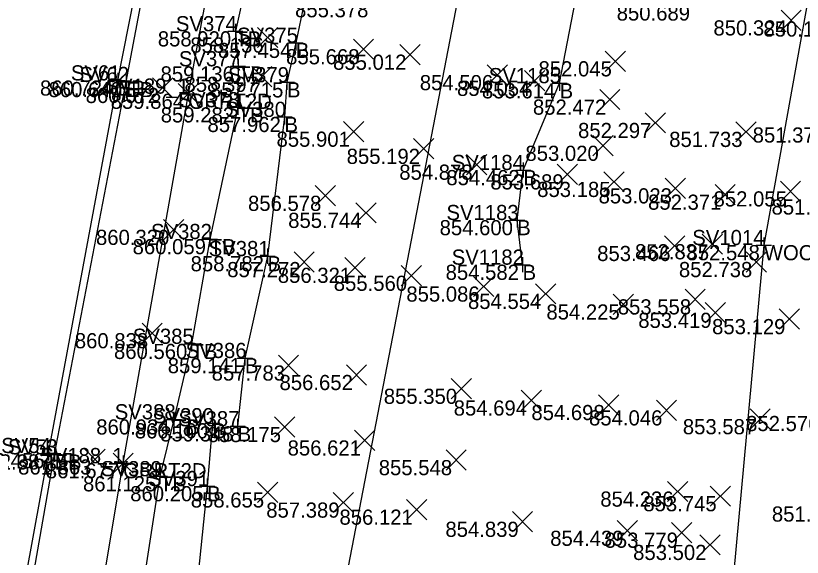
# Model space of a CAD drawing. Extents: x 2228183 to 2230895, y 679226 to 682223.
# Drawn here: x 2228291.3 to 2228343.2, y 680434.6 to 680470.3 of the extents above; entities that cross this region are included whole.
import ezdxf

# ---------------------------------------------------------------- set-up
doc = ezdxf.new("R2010")
doc.units = 0
for name, color, linetype in [('PV_X_EOP', 7, 'Continuous'), ('PV_X_Shoulder_Aggregate', 7, 'Continuous'), ('RD_X_GR_Rt', 7, 'Continuous'), ('SC_Scratch1', 7, 'Continuous'), ('SV_P_Control_Cells_Set', 7, 'Continuous'), ('SV_X_Break_Lines', 7, 'Continuous'), ('SV_X_Random_Point', 7, 'Continuous'), ('SV_X_Shot_Marker', 7, 'Continuous'), ('SV_X_Text_Comment', 7, 'Continuous'), ('SV_X_Top_of_Bank', 7, 'Continuous'), ('UT_X_Telecom', 7, 'Continuous'), ('VG_X_Tree_Line_Rt', 7, 'Continuous')]:
    doc.layers.add(name, color=color, linetype=linetype)

msp = doc.modelspace()

# ---------------------------------------------------------------- linework, layer by layer
at = {"layer": 'PV_X_EOP'}
msp.add_lwpolyline([(2228272.958, 680193.788), (2228272.514, 680218.749), (2228272.761, 680243.66), (2228273.456, 680268.53), (2228274.726, 680293.686), (2228276.435, 680318.586), (2228278.817, 680343.424), (2228281.861, 680368.095), (2228285.158, 680392.512), (2228289.018, 680417.009), (2228293.5, 680441.465), (2228298.055, 680466.05), (2228302.846, 680490.329), (2228307.636, 680514.848), (2228312.366, 680539.332), (2228317.173, 680563.701), (2228322.066, 680588.07), (2228326.883, 680612.686), (2228331.837, 680637.002), (2228336.903, 680661.667), (2228341.796, 680685.984)], dxfattribs=at)
at = {"layer": 'PV_X_Shoulder_Aggregate'}
msp.add_lwpolyline([(2228273.386, 680193.772), (2228272.957, 680218.691), (2228273.264, 680243.644), (2228274.133, 680268.478), (2228275.472, 680293.621), (2228277.239, 680318.511), (2228279.649, 680343.317), (2228282.622, 680367.988), (2228285.854, 680392.371), (2228289.575, 680416.853), (2228293.89, 680441.38), (2228298.61, 680465.949), (2228303.2, 680490.238), (2228308.065, 680514.741), (2228313.026, 680539.169), (2228317.996, 680563.53), (2228322.869, 680587.896), (2228327.71, 680612.549), (2228332.443, 680636.855), (2228337.368, 680661.526), (2228342.398, 680685.817)], dxfattribs=at)
at = {"layer": 'RD_X_GR_Rt'}
msp.add_lwpolyline([(2228290.359, 680391.22), (2228294.274, 680415.932), (2228298.414, 680440.801), (2228302.718, 680465.177), (2228307.188, 680489.321), (2228312.206, 680513.859), (2228316.706, 680538.587), (2228321.519, 680562.878), (2228326.574, 680587.113), (2228331.32, 680611.864), (2228336.079, 680636.156), (2228341.093, 680660.882), (2228346.244, 680685.06), (2228350.849, 680709.572), (2228355.751, 680733.95), (2228357.804, 680743.718), (2228360.585, 680755.706), (2228364.08, 680768.892), (2228368.125, 680781.145)], dxfattribs=at)
at = {"layer": 'SV_X_Break_Lines'}
for points in [[(2228314.747, 680495.992), (2228314.241, 680492.773), (2228314.211, 680488.538), (2228311.578, 680478.889), (2228311.017, 680474.372), (2228309.793, 680468.535), (2228309.215, 680465.931), (2228309.05, 680463.646), (2228307.936, 680454.458), (2228306.438, 680447.736), (2228305.961, 680443.231)], [(2228324.748, 680453.895), (2228324.393, 680456.839), (2228324.797, 680460.14), (2228327.19, 680465.87), (2228328.374, 680472.025), (2228328.363, 680475.549), (2228327.9, 680480.992), (2228324.768, 680483.725), (2228321.985, 680484.931)], [(2228304.297, 680443.433), (2228303.951, 680439.284), (2228303.202, 680431.998), (2228302.174, 680428.001), (2228301.552, 680423.556), (2228300.767, 680417.736), (2228301.038, 680414.553), (2228299.654, 680408.328), (2228299.055, 680402.795), (2228298.646, 680389.665)]]:
    msp.add_lwpolyline(points, dxfattribs=at)
at = {"layer": 'SV_X_Random_Point'}
for p, q in [((2228341.786, 680469.35), (2228343.12, 680470.685)), ((2228341.786, 680470.685), (2228343.12, 680469.35)), ((2228307.28, 680468.218), (2228308.614, 680469.553)), ((2228307.28, 680469.553), (2228308.614, 680468.218)), ((2228313.594, 680467.448), (2228314.928, 680468.783)), ((2228313.594, 680468.783), (2228314.928, 680467.448)), ((2228316.662, 680467.088), (2228317.996, 680468.423)), ((2228316.662, 680468.423), (2228317.996, 680467.088)), ((2228330.203, 680466.652), (2228331.537, 680467.987)), ((2228330.203, 680467.987), (2228331.537, 680466.652)), ((2228306.891, 680465.627), (2228308.225, 680466.962)), ((2228306.891, 680466.962), (2228308.225, 680465.627)), ((2228322.409, 680465.74), (2228323.743, 680467.075)), ((2228322.409, 680467.075), (2228323.743, 680465.74)), ((2228300.349, 680464.895), (2228301.683, 680466.23)), ((2228300.349, 680466.23), (2228301.683, 680464.895)), ((2228324.88, 680465.362), (2228326.214, 680466.697)), ((2228324.88, 680466.697), (2228326.214, 680465.362)), ((2228302.051, 680464.51), (2228303.385, 680465.845)), ((2228302.051, 680465.845), (2228303.385, 680464.51)), ((2228329.836, 680464.125), (2228331.17, 680465.46)), ((2228329.836, 680465.46), (2228331.17, 680464.125)), ((2228332.835, 680462.584), (2228334.169, 680463.919)), ((2228332.835, 680463.919), (2228334.169, 680462.584)), ((2228312.942, 680462.008), (2228314.276, 680463.343)), ((2228312.942, 680463.343), (2228314.276, 680462.008)), ((2228338.811, 680461.994), (2228340.145, 680463.329)), ((2228338.811, 680463.329), (2228340.145, 680461.994)), ((2228317.557, 680460.876), (2228318.891, 680462.211)), ((2228317.557, 680462.211), (2228318.891, 680460.876)), ((2228329.384, 680461.077), (2228330.718, 680462.412)), ((2228329.384, 680462.412), (2228330.718, 680461.077)), ((2228321.052, 680459.832), (2228322.386, 680461.167)), ((2228321.052, 680461.167), (2228322.386, 680459.832)), ((2228327.039, 680459.191), (2228328.373, 680460.526)), ((2228327.039, 680460.526), (2228328.373, 680459.191)), ((2228330.115, 680458.694), (2228331.449, 680460.029)), ((2228330.115, 680460.029), (2228331.449, 680458.694)), ((2228334.156, 680458.269), (2228335.49, 680459.604)), ((2228334.156, 680459.604), (2228335.49, 680458.269)), ((2228311.08, 680457.776), (2228312.414, 680459.111)), ((2228311.08, 680459.111), (2228312.414, 680457.776)), ((2228337.435, 680457.853), (2228338.769, 680459.188)), ((2228337.435, 680459.188), (2228338.769, 680457.853)), ((2228341.742, 680458.068), (2228343.076, 680459.403)), ((2228341.742, 680459.403), (2228343.076, 680458.068)), ((2228313.751, 680456.651), (2228315.085, 680457.986)), ((2228313.751, 680457.986), (2228315.085, 680456.651)), ((2228301.072, 680455.531), (2228302.406, 680456.866)), ((2228301.072, 680456.866), (2228302.406, 680455.531)), ((2228336.586, 680454.581), (2228337.92, 680455.916)), ((2228336.586, 680455.916), (2228337.92, 680454.581)), ((2228334.103, 680454.469), (2228335.437, 680455.804)), ((2228334.103, 680455.804), (2228335.437, 680454.469)), ((2228309.684, 680453.404), (2228311.018, 680454.739)), ((2228309.684, 680454.739), (2228311.018, 680453.404)), ((2228313.027, 680453.027), (2228314.361, 680454.362)), ((2228313.027, 680454.362), (2228314.361, 680453.027)), ((2228339.488, 680453.406), (2228340.822, 680454.741)), ((2228339.488, 680454.741), (2228340.822, 680453.406)), ((2228316.748, 680452.501), (2228318.082, 680453.836)), ((2228316.748, 680453.836), (2228318.082, 680452.501)), ((2228321.522, 680451.79), (2228322.856, 680453.125)), ((2228321.522, 680453.125), (2228322.856, 680451.79)), ((2228325.603, 680451.305), (2228326.937, 680452.64)), ((2228325.603, 680452.64), (2228326.937, 680451.305)), ((2228335.457, 680450.944), (2228336.791, 680452.279)), ((2228335.457, 680452.279), (2228336.791, 680450.944)), ((2228330.722, 680450.609), (2228332.056, 680451.944)), ((2228330.722, 680451.944), (2228332.056, 680450.609)), ((2228336.793, 680450.057), (2228338.127, 680451.392)), ((2228336.793, 680451.392), (2228338.127, 680450.057)), ((2228341.659, 680449.642), (2228342.993, 680450.977)), ((2228341.659, 680450.977), (2228342.993, 680449.642)), ((2228299.663, 680448.711), (2228300.997, 680450.046)), ((2228299.663, 680450.046), (2228300.997, 680448.711)), ((2228308.65, 680446.58), (2228309.984, 680447.915)), ((2228308.65, 680447.915), (2228309.984, 680446.58)), ((2228313.131, 680445.953), (2228314.465, 680447.288)), ((2228313.131, 680447.288), (2228314.465, 680445.953)), ((2228320.045, 680445.043), (2228321.379, 680446.378)), ((2228320.045, 680446.378), (2228321.379, 680445.043)), ((2228324.662, 680444.271), (2228325.996, 680445.606)), ((2228324.662, 680445.606), (2228325.996, 680444.271)), ((2228329.762, 680443.972), (2228331.096, 680445.307)), ((2228329.762, 680445.307), (2228331.096, 680443.972)), ((2228333.567, 680443.62), (2228334.901, 680444.955)), ((2228333.567, 680444.955), (2228334.901, 680443.62)), ((2228339.742, 680443.038), (2228341.076, 680444.373)), ((2228339.742, 680444.373), (2228341.076, 680443.038)), ((2228308.39, 680442.522), (2228309.724, 680443.857)), ((2228308.39, 680443.857), (2228309.724, 680442.522)), ((2228313.674, 680441.635), (2228315.008, 680442.97)), ((2228313.674, 680442.97), (2228315.008, 680441.635)), ((2228295.888, 680440.382), (2228297.222, 680441.717)), ((2228295.888, 680441.717), (2228297.222, 680440.382)), ((2228297.747, 680440.134), (2228299.081, 680441.469)), ((2228297.747, 680441.469), (2228299.081, 680440.134)), ((2228319.7, 680440.337), (2228321.034, 680441.672)), ((2228319.7, 680441.672), (2228321.034, 680440.337)), ((2228307.277, 680438.205), (2228308.611, 680439.54)), ((2228307.277, 680439.54), (2228308.611, 680438.205)), ((2228334.308, 680438.262), (2228335.642, 680439.597)), ((2228334.308, 680439.597), (2228335.642, 680438.262)), ((2228337.111, 680437.957), (2228338.445, 680439.292)), ((2228337.111, 680439.292), (2228338.445, 680437.957)), ((2228312.266, 680437.536), (2228313.6, 680438.871)), ((2228312.266, 680438.871), (2228313.6, 680437.536)), ((2228317.092, 680437.07), (2228318.426, 680438.405)), ((2228317.092, 680438.405), (2228318.426, 680437.07)), ((2228324.078, 680436.269), (2228325.412, 680437.604)), ((2228324.078, 680437.604), (2228325.412, 680436.269)), ((2228330.987, 680435.674), (2228332.321, 680437.009)), ((2228330.987, 680437.009), (2228332.321, 680435.674)), ((2228334.57, 680435.55), (2228335.904, 680436.885)), ((2228334.57, 680436.885), (2228335.904, 680435.55)), ((2228336.443, 680434.743), (2228337.777, 680436.078)), ((2228336.443, 680436.078), (2228337.777, 680434.743))]:
    msp.add_line(p, q, dxfattribs=at)
at = {"layer": 'SV_X_Shot_Marker'}
for p, q in [((2228305.315, 680469.295), (2228306.315, 680469.295)), ((2228305.815, 680469.795), (2228305.815, 680468.795)), ((2228305.815, 680469.295), (2228305.815, 680469.295)), ((2228309.793, 680469.035), (2228309.793, 680468.035)), ((2228309.293, 680468.535), (2228310.293, 680468.535)), ((2228309.793, 680468.535), (2228309.793, 680468.535)), ((2228305.987, 680467.483), (2228305.987, 680466.483)), ((2228305.487, 680466.983), (2228306.487, 680466.983)), ((2228305.987, 680466.983), (2228305.987, 680466.983)), ((2228298.055, 680466.55), (2228298.055, 680465.55)), ((2228298.61, 680466.449), (2228298.61, 680465.449)), ((2228309.215, 680466.431), (2228309.215, 680465.431)), ((2228327.19, 680466.37), (2228327.19, 680465.37)), ((2228297.555, 680466.05), (2228298.555, 680466.05)), ((2228298.055, 680466.05), (2228298.055, 680466.05)), ((2228298.11, 680465.949), (2228299.11, 680465.949)), ((2228298.61, 680465.949), (2228298.61, 680465.949)), ((2228302.718, 680465.677), (2228302.718, 680464.677)), ((2228308.715, 680465.931), (2228309.715, 680465.931)), ((2228309.215, 680465.931), (2228309.215, 680465.931)), ((2228326.69, 680465.87), (2228327.69, 680465.87)), ((2228327.19, 680465.87), (2228327.19, 680465.87)), ((2228302.218, 680465.177), (2228303.218, 680465.177)), ((2228302.718, 680465.177), (2228302.718, 680465.177)), ((2228305.966, 680464.779), (2228305.966, 680463.779)), ((2228305.466, 680464.279), (2228306.466, 680464.279)), ((2228305.966, 680464.279), (2228305.966, 680464.279)), ((2228309.05, 680464.146), (2228309.05, 680463.146)), ((2228308.55, 680463.646), (2228309.55, 680463.646)), ((2228309.05, 680463.646), (2228309.05, 680463.646)), ((2228324.797, 680460.64), (2228324.797, 680459.64)), ((2228324.297, 680460.14), (2228325.297, 680460.14)), ((2228324.797, 680460.14), (2228324.797, 680460.14)), ((2228324.393, 680457.339), (2228324.393, 680456.339)), ((2228323.893, 680456.839), (2228324.893, 680456.839)), ((2228324.393, 680456.839), (2228324.393, 680456.839)), ((2228304.125, 680456.086), (2228304.125, 680455.086)), ((2228303.625, 680455.586), (2228304.625, 680455.586)), ((2228304.125, 680455.586), (2228304.125, 680455.586)), ((2228340.655, 680455.686), (2228340.655, 680454.686)), ((2228307.936, 680454.958), (2228307.936, 680453.958)), ((2228340.155, 680455.186), (2228341.155, 680455.186)), ((2228340.655, 680455.186), (2228340.655, 680455.186)), ((2228307.436, 680454.458), (2228308.436, 680454.458)), ((2228307.936, 680454.458), (2228307.936, 680454.458)), ((2228324.748, 680454.395), (2228324.748, 680453.395)), ((2228324.248, 680453.895), (2228325.248, 680453.895)), ((2228324.748, 680453.895), (2228324.748, 680453.895)), ((2228302.925, 680449.172), (2228302.925, 680448.172)), ((2228302.425, 680448.672), (2228303.425, 680448.672)), ((2228302.925, 680448.672), (2228302.925, 680448.672)), ((2228306.438, 680448.236), (2228306.438, 680447.236)), ((2228305.938, 680447.736), (2228306.938, 680447.736)), ((2228306.438, 680447.736), (2228306.438, 680447.736)), ((2228301.763, 680444.189), (2228301.763, 680443.189)), ((2228304.297, 680443.933), (2228304.297, 680442.933)), ((2228301.263, 680443.689), (2228302.263, 680443.689)), ((2228301.763, 680443.689), (2228301.763, 680443.689)), ((2228303.797, 680443.433), (2228304.797, 680443.433)), ((2228304.297, 680443.433), (2228304.297, 680443.433)), ((2228305.961, 680443.731), (2228305.961, 680442.731)), ((2228305.461, 680443.231), (2228306.461, 680443.231)), ((2228305.961, 680443.231), (2228305.961, 680443.231)), ((2228293.5, 680441.965), (2228293.5, 680440.965)), ((2228293.89, 680441.88), (2228293.89, 680440.88)), ((2228293, 680441.465), (2228294, 680441.465)), ((2228293.39, 680441.38), (2228294.39, 680441.38)), ((2228293.5, 680441.465), (2228293.5, 680441.465)), ((2228293.89, 680441.38), (2228293.89, 680441.38)), ((2228298.414, 680441.301), (2228298.414, 680440.301)), ((2228297.914, 680440.801), (2228298.914, 680440.801)), ((2228298.414, 680440.801), (2228298.414, 680440.801)), ((2228300.838, 680440.438), (2228300.838, 680439.438)), ((2228300.338, 680439.938), (2228301.338, 680439.938)), ((2228300.838, 680439.938), (2228300.838, 680439.938)), ((2228303.951, 680439.784), (2228303.951, 680438.784)), ((2228303.451, 680439.284), (2228304.451, 680439.284)), ((2228303.951, 680439.284), (2228303.951, 680439.284))]:
    msp.add_line(p, q, dxfattribs=at)
at = {"layer": 'SV_X_Top_of_Bank'}
msp.add_lwpolyline([(2228313.24, 680508.044), (2228312.693, 680504.139), (2228311.655, 680498.217), (2228309.921, 680488.581), (2228308.107, 680479.863), (2228307.043, 680474.864), (2228305.815, 680469.295), (2228305.987, 680466.983), (2228305.966, 680464.279), (2228304.125, 680455.586), (2228302.925, 680448.672), (2228301.763, 680443.689), (2228300.838, 680439.938), (2228299.782, 680433.077), (2228298.614, 680423.72), (2228298.016, 680421.452), (2228298.283, 680417.737), (2228297.819, 680415.042)], dxfattribs=at)
at = {"layer": 'UT_X_Telecom'}
msp.add_lwpolyline([(2228306.801, 680400.49), (2228337.511, 680559.672), (2228349.317, 680620.055), (2228359.383, 680671.523), (2228365.58, 680702.692), (2228381.421, 680781.425)], dxfattribs=at)
at = {"layer": 'VG_X_Tree_Line_Rt'}
msp.add_lwpolyline([(2228410.452, 680773.345), (2228402.142, 680728.483), (2228403.602, 680691.208), (2228374.606, 680596.133), (2228370.969, 680582.119), (2228367.614, 680567.008), (2228346.3, 680486.661), (2228340.655, 680455.186), (2228334.048, 680383.235)], dxfattribs=at)

# ---------------------------------------------------------------- texts
at = {"layer": 'SC_Scratch1'}
for s, p in [('855.378', (2228309.75, 680470.218)), ('850.689', (2228330.953, 680470.002)), ('850.324', (2228337.331, 680469.017)), ('850.107', (2228340.628, 680468.944)), ('858.920', (2228300.701, 680468.295)), ('858.136', (2228302.843, 680467.885)), ('857.454', (2228304.671, 680467.535)), ('855.668', (2228309.161, 680467.115)), ('855.012', (2228312.256, 680466.755)), ('852.045', (2228325.8, 680466.319)), ('859.136', (2228300.883, 680465.983)), ('858.397', (2228302.462, 680465.294)), ('854.506', (2228317.972, 680465.407)), ('860.724', (2228292.933, 680465.05)), ('860.640', (2228293.496, 680464.949)), ('857.715', (2228304.145, 680464.931)), ('854.054', (2228320.425, 680465.029)), ('853.614', (2228322.068, 680464.87)), ('860.072', (2228295.943, 680464.562)), ('859.864', (2228297.596, 680464.177)), ('859.864', (2228297.596, 680464.177)), ('852.472', (2228325.43, 680463.792)), ('859.282', (2228300.893, 680463.279)), ('857.962', (2228303.977, 680462.646)), ('852.297', (2228328.406, 680462.251)), ('855.901', (2228308.527, 680461.675)), ('851.733', (2228334.414, 680461.661)), ('851.372', (2228339.917, 680461.952)), ('855.192', (2228313.151, 680460.543)), ('853.020', (2228324.937, 680460.744)), ('854.878', (2228316.619, 680459.499)), ('854.462', (2228319.724, 680459.14)), ('853.689', (2228322.622, 680458.858)), ('853.185', (2228325.712, 680458.361)), ('853.023', (2228329.759, 680457.936)), ('856.578', (2228306.647, 680457.443)), ('852.371', (2228333.02, 680457.52)), ('852.055', (2228337.339, 680457.735)), ('851.720', (2228341.162, 680457.202)), ('855.744', (2228309.296, 680456.318)), ('854.600', (2228319.279, 680455.839)), ('860.320', (2228296.625, 680455.198)), ('860.059', (2228299.041, 680454.586)), ('853.466', (2228329.666, 680454.136)), ('852.837', (2228332.157, 680454.248)), ('852.548', (2228335.555, 680454.186)), ('858.782', (2228302.863, 680453.458)), ('857.272', (2228305.278, 680453.071)), ('854.582', (2228319.675, 680452.895)), ('852.738', (2228335.055, 680453.073)), ('856.321', (2228308.612, 680452.694)), ('855.560', (2228312.301, 680452.168)), ('855.086', (2228317.085, 680451.457)), ('854.554', (2228321.148, 680450.972)), ('854.225', (2228326.319, 680450.276)), ('853.558', (2228331.024, 680450.611)), ('853.419', (2228332.376, 680449.724)), ('853.129', (2228337.242, 680449.309)), ('860.838', (2228295.23, 680448.378)), ('860.560', (2228297.811, 680447.672)), ('859.141', (2228301.356, 680446.736)), ('857.783', (2228304.253, 680446.247)), ('856.652', (2228308.725, 680445.62)), ('855.350', (2228315.598, 680444.71)), ('854.694', (2228320.207, 680443.938)), ('854.698', (2228325.329, 680443.639)), ('854.046', (2228329.13, 680443.287)), ('852.576', (2228339.484, 680442.915)), ('860.934', (2228296.641, 680442.689)), ('860.100', (2228299.183, 680442.433)), ('853.587', (2228335.313, 680442.705)), ('859.348', (2228300.861, 680442.231)), ('858.175', (2228303.987, 680442.189)), ('856.621', (2228309.259, 680441.302)), ('862.456', (2228288.396, 680440.465)), ('862.387', (2228288.794, 680440.38)), ('861.863', (2228291.491, 680440.049)), ('861.677', (2228293.318, 680439.801)), ('861.677', (2228293.318, 680439.801)), ('855.548', (2228315.267, 680440.004)), ('861.125', (2228295.768, 680438.938)), ('860.205', (2228298.881, 680438.284)), ('858.655', (2228302.874, 680437.872)), ('854.236', (2228329.871, 680437.929)), ('857.389', (2228307.849, 680437.203)), ('853.745', (2228332.708, 680437.624)), ('856.121', (2228312.677, 680436.737)), ('851.576', (2228341.184, 680436.942)), ('854.839', (2228319.661, 680435.936)), ('854.439', (2228326.57, 680435.341)), ('853.779', (2228330.153, 680435.217)), ('853.502', (2228332.037, 680434.41))]:
    msp.add_text(s, height=1, dxfattribs=at).set_placement(p)
at = {"layer": 'SV_P_Control_Cells_Set'}
for s, p in [('SV374', (2228301.893, 680469.295)), ('SV375', (2228305.923, 680468.535)), ('SV377', (2228302.091, 680466.983)), ('SV61', (2228294.971, 680466.05)), ('SV62', (2228295.535, 680465.949)), ('SV379', (2228305.331, 680465.931)), ('SV1185', (2228322.521, 680465.87)), ('SV189_1', (2228297.253, 680465.177)), ('SV378', (2228302.066, 680464.279)), ('SV380', (2228305.136, 680463.646)), ('SV1184', (2228320.077, 680460.14)), ('SV1183', (2228319.731, 680456.839)), ('SV382', (2228300.252, 680455.586)), ('SV1014', (2228335.935, 680455.186)), ('SV381', (2228304.054, 680454.458)), ('SV1182', (2228320.077, 680453.895)), ('SV385', (2228299.055, 680448.672)), ('SV386', (2228302.534, 680447.736)), ('SV388', (2228297.863, 680443.689)), ('SV390', (2228300.383, 680443.433)), ('SV387', (2228302.065, 680443.231)), ('SV54', (2228290.376, 680441.465)), ('SV53', (2228290.824, 680441.38)), ('SV188_1', (2228292.949, 680440.801)), ('SV389', (2228296.954, 680439.938)), ('SV391', (2228300.069, 680439.284))]:
    msp.add_text(s, height=1, dxfattribs=at).set_placement(p)
at = {"layer": 'SV_X_Text_Comment'}
for s, p in [('TB', (2228305.815, 680468.295)), ('B', (2228309.793, 680467.535)), ('TB', (2228305.987, 680465.983)), ('EP', (2228298.055, 680465.05)), ('EB', (2228298.61, 680464.949)), ('B', (2228309.215, 680464.931)), ('B', (2228327.19, 680464.87)), ('GRRT2D', (2228302.718, 680464.177)), ('TB', (2228305.966, 680463.279)), ('B', (2228309.05, 680462.646)), ('B', (2228324.797, 680459.14)), ('B', (2228324.393, 680455.839)), ('TB', (2228304.125, 680454.586)), ('WOODSR', (2228340.655, 680454.186)), ('B', (2228307.936, 680453.458)), ('B', (2228324.748, 680452.895)), ('TB', (2228302.925, 680447.672)), ('B', (2228306.438, 680446.736)), ('TB', (2228301.763, 680442.689)), ('B', (2228304.297, 680442.433)), ('B', (2228305.961, 680442.231)), ('EP', (2228293.5, 680440.465)), ('EB', (2228293.89, 680440.38)), ('GRRT2D', (2228298.414, 680439.801)), ('TB', (2228300.838, 680438.938)), ('B', (2228303.951, 680438.284))]:
    msp.add_text(s, height=1, dxfattribs=at).set_placement(p)

doc.saveas('drawing.dxf')
